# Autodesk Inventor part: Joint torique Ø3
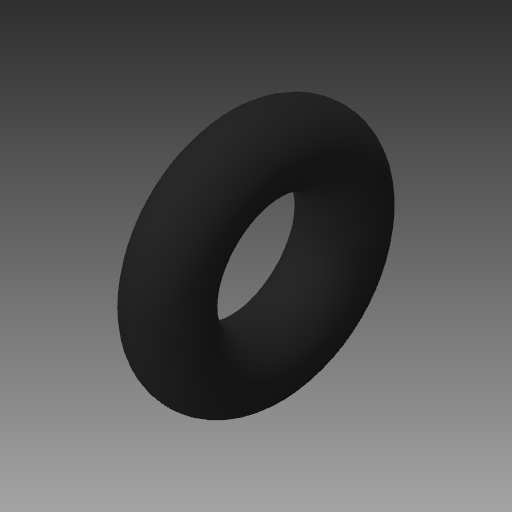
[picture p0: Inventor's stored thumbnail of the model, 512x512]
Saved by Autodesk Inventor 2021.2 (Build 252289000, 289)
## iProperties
Created: 2018-06
Part Number: Joint torique Ø3
Material: Caoutchouc
Document SubType Name: Modeling
Designer: Fabian Perrée
Density: 0.93 g/cm^3
Appearance: Caoutchouc - Noir
Author: Fabian Perrée
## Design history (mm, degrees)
sketch "Esquisse1"
  geometry: L1 (-2.1, 0)-(2.1, 0) reference; C1 r 1.5 at (0, 3.75); 1 further point
  constraints: 1 centre point, 1 vertical alignment
  dimensions: "d0" = 3 diameter of C1; "d1" = 3.75 distance of point (0, 0) C1.centre
revolve "Révolution1" sketch "Esquisse1" stored, may be unused: angle "d2" = 90 deg
node "Solide1"
